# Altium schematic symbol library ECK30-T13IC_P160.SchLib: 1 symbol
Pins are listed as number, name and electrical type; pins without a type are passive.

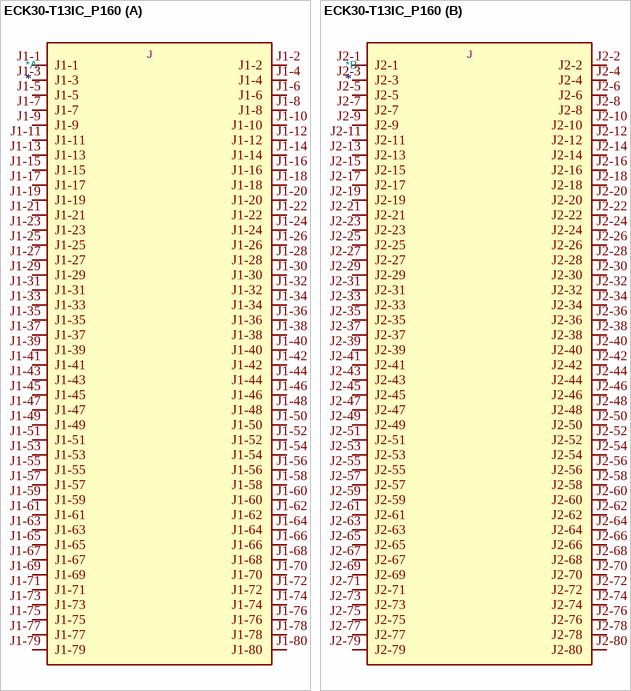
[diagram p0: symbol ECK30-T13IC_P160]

## ECK30-T13IC_P160
designator *  Reference: J
part A pins: J1-1, J1-2, J1-3, J1-4, J1-5, J1-6, J1-7, J1-8, J1-9, J1-10, J1-11, J1-12, J1-13, J1-14, J1-15, J1-16, J1-17, J1-18, J1-19, J1-20, J1-21, J1-22, J1-23, J1-24, J1-25, J1-26, J1-27, J1-28, J1-29, J1-30, J1-31, J1-32, J1-33, J1-34, J1-35, J1-36, J1-37, J1-38, J1-39, J1-40, J1-41, J1-42, J1-43, J1-44, J1-45, J1-46, J1-47, J1-48, J1-49, J1-50, J1-51, J1-52, J1-53, J1-54, J1-55, J1-56, J1-57, J1-58, J1-59, J1-60, J1-61, J1-62, J1-63, J1-64, J1-65, J1-66, J1-67, J1-68, J1-69, J1-70, J1-71, J1-72, J1-73, J1-74, J1-75, J1-76, J1-77, J1-78, J1-79, J1-80
part B pins: J2-1, J2-2, J2-3, J2-4, J2-5, J2-6, J2-7, J2-8, J2-9, J2-10, J2-11, J2-12, J2-13, J2-14, J2-15, J2-16, J2-17, J2-18, J2-19, J2-20, J2-21, J2-22, J2-23, J2-24, J2-25, J2-26, J2-27, J2-28, J2-29, J2-30, J2-31, J2-32, J2-33, J2-34, J2-35, J2-36, J2-37, J2-38, J2-39, J2-40, J2-41, J2-42, J2-43, J2-44, J2-45, J2-46, J2-47, J2-48, J2-49, J2-50, J2-51, J2-52, J2-53, J2-54, J2-55, J2-56, J2-57, J2-58, J2-59, J2-60, J2-61, J2-62, J2-63, J2-64, J2-65, J2-66, J2-67, J2-68, J2-69, J2-70, J2-71, J2-72, J2-73, J2-74, J2-75, J2-76, J2-77, J2-78, J2-79, J2-80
